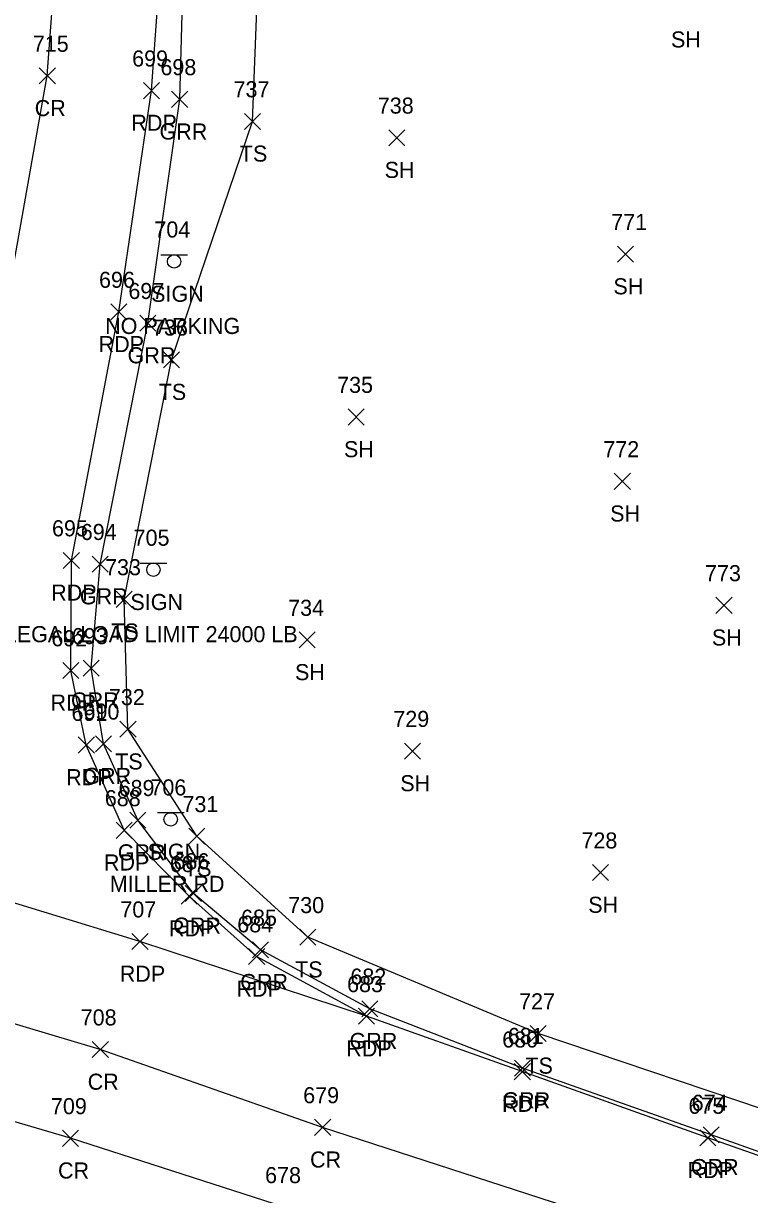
# Model space of a CAD drawing. Extents: x 1629176 to 1637209, y 606063 to 610167.
# Drawn here: x 1629985.1 to 1630075.4, y 606927.3 to 607073 of the extents above; entities that cross this region are included whole.
import ezdxf

# ---------------------------------------------------------------- set-up
doc = ezdxf.new("R2010")
doc.units = 0
for name, color, linetype in [('L_A', 7, 'Continuous'), ('L_I', 7, 'Continuous'), ('L_TIC', 7, 'Continuous'), ('LELB', 7, 'Continuous'), ('P_A', 7, 'Continuous'), ('P_I', 7, 'Continuous'), ('P_TIC', 7, 'Continuous'), ('PET', 7, 'Continuous'), ('PRC', 7, 'Continuous'), ('R_A', 7, 'Continuous'), ('R_I', 7, 'Continuous'), ('R_TIC', 7, 'Continuous'), ('RGR', 7, 'Continuous'), ('S_A', 7, 'Continuous'), ('S_C', 7, 'Continuous'), ('S_I', 7, 'Continuous'), ('SSGN', 7, 'Continuous')]:
    doc.layers.add(name, color=color, linetype=linetype)

msp = doc.modelspace()

# ---------------------------------------------------------------- linework, layer by layer
at = {"layer": 'L_TIC'}
for points in [[(1630012.65, 607059.81), (1630014.65, 607061.81)], [(1630014.65, 607059.81), (1630012.65, 607061.81)], [(1630030.58, 607057.78), (1630032.58, 607059.78)], [(1630032.58, 607057.78), (1630030.58, 607059.78)], [(1630059.03, 607043.3), (1630061.03, 607045.3)], [(1630061.03, 607043.3), (1630059.03, 607045.3)], [(1630002.56, 607030.17), (1630004.56, 607032.17)], [(1630004.56, 607030.17), (1630002.56, 607032.17)], [(1630025.52, 607023.04), (1630027.52, 607025.04)], [(1630027.52, 607023.04), (1630025.52, 607025.04)], [(1630058.63, 607015.04), (1630060.63, 607017.04)], [(1630060.63, 607015.04), (1630058.63, 607017.04)], [(1629996.66, 607000.36), (1629998.66, 607002.36)], [(1629998.66, 607000.36), (1629996.66, 607002.36)], [(1630071.27, 606999.62), (1630073.27, 607001.62)], [(1630073.27, 606999.62), (1630071.27, 607001.62)], [(1630019.43, 606995.31), (1630021.43, 606997.31)], [(1630021.43, 606995.31), (1630019.43, 606997.31)], [(1629997.15, 606984.2), (1629999.15, 606986.2)], [(1629999.15, 606984.2), (1629997.15, 606986.2)], [(1630032.52, 606981.49), (1630034.52, 606983.49)], [(1630034.52, 606981.49), (1630032.52, 606983.49)], [(1630005.71, 606970.89), (1630007.71, 606972.89)], [(1630007.71, 606970.89), (1630005.71, 606972.89)], [(1630055.9, 606966.37), (1630057.9, 606968.37)], [(1630057.9, 606966.37), (1630055.9, 606968.37)], [(1630019.53, 606958.33), (1630021.53, 606960.33)], [(1630021.53, 606958.33), (1630019.53, 606960.33)], [(1630048.16, 606946.36), (1630050.16, 606948.36)], [(1630050.16, 606946.36), (1630048.16, 606948.36)]]:
    msp.add_lwpolyline(points, dxfattribs=at)
at = {"layer": 'LELB'}
msp.add_lwpolyline([(1630084.2, 606935.53), (1630049.16, 606947.36), (1630020.53, 606959.33), (1630006.71, 606971.89), (1629998.15, 606985.2), (1629997.66, 607001.36), (1630003.56, 607031.17), (1630013.65, 607060.81), (1630014.9, 607093.95), (1630014.94, 607124.25), (1630010.97, 607149.73), (1630004.22, 607196.84), (1629997.94, 607243.02), (1629990.5, 607295.3), (1629983.84, 607333.53), (1629977.49, 607374.66), (1629974.09, 607413.89), (1629967.52, 607447.68), (1629960.93, 607485.98), (1629955.08, 607527.79), (1629952.27, 607562.54)], dxfattribs=at)
at = {"layer": 'P_TIC'}
for points in [[(1629987.12, 607065.47), (1629989.12, 607067.47)], [(1629989.12, 607065.47), (1629987.12, 607067.47)], [(1630000.08, 607063.64), (1630002.08, 607065.64)], [(1630002.08, 607063.64), (1630000.08, 607065.64)], [(1629996.01, 607036.11), (1629998.01, 607038.11)], [(1629998.01, 607036.11), (1629996.01, 607038.11)], [(1629990.11, 607005.2), (1629992.11, 607007.2)], [(1629992.11, 607005.2), (1629990.11, 607007.2)], [(1629990.03, 606991.52), (1629992.03, 606993.52)], [(1629992.03, 606991.52), (1629990.03, 606993.52)], [(1629991.97, 606982.24), (1629993.97, 606984.24)], [(1629993.97, 606982.24), (1629991.97, 606984.24)], [(1629996.68, 606971.63), (1629998.68, 606973.63)], [(1629998.68, 606971.63), (1629996.68, 606973.63)], [(1630004.77, 606963.44), (1630006.77, 606965.44)], [(1630006.77, 606963.44), (1630004.77, 606965.44)], [(1629998.64, 606957.79), (1630000.64, 606959.79)], [(1630000.64, 606957.79), (1629998.64, 606959.79)], [(1630013.15, 606955.94), (1630015.15, 606957.94)], [(1630015.15, 606955.94), (1630013.15, 606957.94)], [(1630026.81, 606948.5), (1630028.81, 606950.5)], [(1630028.81, 606948.5), (1630026.81, 606950.5)], [(1630026.81, 606948.5), (1630028.81, 606950.5)], [(1630028.81, 606948.5), (1630026.81, 606950.5)], [(1629993.71, 606944.36), (1629995.71, 606946.36)], [(1629995.71, 606944.36), (1629993.71, 606946.36)], [(1630046.19, 606941.61), (1630048.19, 606943.61)], [(1630048.19, 606941.61), (1630046.19, 606943.61)], [(1630021.36, 606934.68), (1630023.36, 606936.68)], [(1630023.36, 606934.68), (1630021.36, 606936.68)], [(1629990.01, 606933.32), (1629992.01, 606935.32)], [(1629992.01, 606933.32), (1629990.01, 606935.32)], [(1630069.26, 606933.37), (1630071.26, 606935.37)], [(1630071.26, 606933.37), (1630069.26, 606935.37)]]:
    msp.add_lwpolyline(points, dxfattribs=at)
at = {"layer": 'PET'}
for points in [[(1630027.81, 606949.5), (1630014.15, 606956.94), (1630005.77, 606964.44), (1629997.68, 606972.63), (1629992.97, 606983.24), (1629991.03, 606992.52), (1629991.11, 607006.2), (1629997.01, 607037.11), (1630001.08, 607064.64), (1630003.41, 607096.82), (1630003.02, 607124.17), (1630001.72, 607150.37), (1629998.35, 607185.15), (1629992.8, 607228.9), (1629986.61, 607277.03), (1629979.67, 607327.82), (1629973.81, 607373.57)], [(1630115.59, 606918.47), (1630070.26, 606934.37), (1630047.19, 606942.61), (1630027.81, 606949.5), (1629999.64, 606958.79), (1629963.88, 606969.73), (1629916.37, 606983.66), (1629883.8, 606991.87), (1629841.7, 607003.38), (1629794.53, 607014.94), (1629751.13, 607024.85), (1629703.98, 607035.26), (1629666.74, 607043.02), (1629621.43, 607051.04), (1629588.28, 607056.93), (1629542.89, 607063.67), (1629493.94, 607070.34), (1629447.94, 607075.86), (1629406.53, 607080.22), (1629360.37, 607084.28), (1629316.73, 607087.48), (1629269.81, 607090.12), (1629227.29, 607092.24), (1629182.92, 607093.47)]]:
    msp.add_lwpolyline(points, dxfattribs=at)
at = {"layer": 'PRC'}
for points in [[(1629963.88, 606969.73), (1629972.76, 606997.52), (1629981.25, 607028.09), (1629988.12, 607066.47), (1629990.62, 607100.29), (1629990.61, 607124.69), (1629989.69, 607149.78), (1629986.77, 607182.68), (1629981.28, 607228.24), (1629975.13, 607276.5), (1629968.07, 607326.63), (1629961.78, 607372.25), (1629956.91, 607408.66), (1629951.88, 607446.34), (1629946.39, 607483.34), (1629940.59, 607526.71), (1629934.53, 607569.1), (1629928.23, 607613.94), (1629922.81, 607653.99), (1629916.48, 607702.82)], [(1630110.18, 606905.77), (1630065.36, 606921.68), (1630022.36, 606935.68), (1629994.71, 606945.36), (1629959.54, 606955.86), (1629913.54, 606969.37), (1629877.41, 606979.26), (1629837.69, 606989.99), (1629791.63, 607000.82), (1629746.42, 607011.44), (1629699.59, 607021.37), (1629664.04, 607028.34), (1629619.43, 607036.79), (1629585.72, 607042.18), (1629539.96, 607049.3), (1629491.45, 607056.02), (1629445.88, 607061.28), (1629404.36, 607066.23), (1629358.89, 607069.49), (1629314.63, 607073.29), (1629269.37, 607075.36), (1629226.58, 607077.32), (1629182.35, 607078.58)], [(1630105.99, 606894.95), (1630061.18, 606910.94), (1630017.61, 606925.74), (1629991.01, 606934.32), (1629955.3, 606944.84), (1629910.77, 606959.12), (1629874.52, 606969.06), (1629834.93, 606979.4), (1629788.74, 606990.13), (1629743.3, 607000.68), (1629697.98, 607010.33), (1629662.17, 607017.56), (1629618.2, 607025.81), (1629583.59, 607031.56), (1629540.4, 607037.95), (1629489.63, 607045.02), (1629444.26, 607050.14), (1629402.79, 607054.66), (1629359.1, 607058.26), (1629313.06, 607061.88), (1629268.47, 607063.97), (1629226.23, 607065.89), (1629182.22, 607066.96)]]:
    msp.add_lwpolyline(points, dxfattribs=at)
at = {"layer": 'R_TIC'}
for points in [[(1630003.58, 607062.56), (1630005.58, 607064.56)], [(1630005.58, 607062.56), (1630003.58, 607064.56)], [(1629999.61, 607034.72), (1630001.61, 607036.72)], [(1630001.61, 607034.72), (1629999.61, 607036.72)], [(1629993.69, 607004.74), (1629995.69, 607006.74)], [(1629995.69, 607004.74), (1629993.69, 607006.74)], [(1629992.57, 606991.79), (1629994.57, 606993.79)], [(1629994.57, 606991.79), (1629992.57, 606993.79)], [(1629994.11, 606982.4), (1629996.11, 606984.4)], [(1629996.11, 606982.4), (1629994.11, 606984.4)], [(1629998.39, 606972.89), (1630000.39, 606974.89)], [(1630000.39, 606972.89), (1629998.39, 606974.89)], [(1630005.28, 606963.78), (1630007.28, 606965.78)], [(1630007.28, 606963.78), (1630005.28, 606965.78)], [(1630013.62, 606956.76), (1630015.62, 606958.76)], [(1630015.62, 606956.76), (1630013.62, 606958.76)], [(1630027.22, 606949.43), (1630029.22, 606951.43)], [(1630029.22, 606949.43), (1630027.22, 606951.43)], [(1630046.22, 606942.05), (1630048.22, 606944.05)], [(1630048.22, 606942.05), (1630046.22, 606944.05)], [(1630069.66, 606933.74), (1630071.66, 606935.74)], [(1630071.66, 606933.74), (1630069.66, 606935.74)]]:
    msp.add_lwpolyline(points, dxfattribs=at)
at = {"layer": 'RGR'}
msp.add_lwpolyline([(1630115.67, 606918.76), (1630070.66, 606934.74), (1630047.22, 606943.05), (1630028.22, 606950.43), (1630014.62, 606957.76), (1630006.28, 606964.78), (1629999.39, 606973.89), (1629995.11, 606983.4), (1629993.57, 606992.79), (1629994.69, 607005.74), (1630000.61, 607035.72), (1630004.58, 607063.56), (1630005.51, 607096.84), (1630005.28, 607124.06), (1630003.63, 607150.96), (1629999.95, 607185.04), (1629994.67, 607228.89), (1629988.47, 607276.39), (1629981.73, 607327.94), (1629975.48, 607374.16), (1629971.69, 607411.49)], dxfattribs=at)
at = {"layer": 'SSGN'}
for p, q in [((1630002.24, 607044.22), (1630005.57, 607044.22)), ((1630003.89, 607043.39), (1630003.89, 607043.39)), ((1629999.67, 607005.88), (1630003, 607005.88)), ((1630001.31, 607005.05), (1630001.31, 607005.05)), ((1630001.81, 606974.83), (1630005.14, 606974.83)), ((1630003.46, 606973.99), (1630003.46, 606973.99))]:
    msp.add_line(p, q, dxfattribs=at)
for centre in [(1630003.89, 607043.39), (1630001.31, 607005.05), (1630003.46, 606973.99)]:
    msp.add_circle(centre, 0.833, dxfattribs=at)

# ---------------------------------------------------------------- texts
at = {"layer": 'L_A'}
for s, p in [('SH', (1630065.68, 607070.01)), ('TS', (1630012.06, 607055.81)), ('SH', (1630030.07, 607053.78)), ('SH', (1630058.52, 607039.3)), ('TS', (1630001.97, 607026.17)), ('SH', (1630025.01, 607019.04)), ('SH', (1630058.11, 607011.04)), ('TS', (1629996.07, 606996.36)), ('SH', (1630070.76, 606995.62)), ('SH', (1630018.92, 606991.31)), ('TS', (1629996.56, 606980.2)), ('SH', (1630032.01, 606977.49)), ('TS', (1630005.12, 606966.89)), ('SH', (1630055.39, 606962.37)), ('TS', (1630018.94, 606954.33)), ('TS', (1630047.57, 606942.36))]:
    msp.add_text(s, height=2, dxfattribs=at).set_placement(p)
at = {"layer": 'L_I'}
for s, p in [('737', (1630011.28, 607063.81)), ('738', (1630029.22, 607061.78)), ('771', (1630058.24, 607047.3)), ('736', (1630001.14, 607034.17)), ('735', (1630024.16, 607027.04)), ('772', (1630057.26, 607019.04)), ('733', (1629995.3, 607004.36)), ('773', (1630069.91, 607003.62)), ('734', (1630018.07, 606999.31)), ('732', (1629995.78, 606988.2)), ('729', (1630031.15, 606985.49)), ('731', (1630004.92, 606974.89)), ('728', (1630054.54, 606970.37)), ('730', (1630018.08, 606962.33)), ('727', (1630046.79, 606950.36))]:
    msp.add_text(s, height=2, dxfattribs=at).set_placement(p)
at = {"layer": 'P_A'}
for s, p in [('CR', (1629986.55, 607061.47)), ('RDP', (1629998.57, 607059.64)), ('RDP', (1629994.5, 607032.11)), ('RDP', (1629988.6, 607001.2)), ('RDP', (1629988.52, 606987.52)), ('RDP', (1629990.46, 606978.24)), ('RDP', (1629995.16, 606967.63)), ('RDP', (1630003.25, 606959.44)), ('RDP', (1629997.13, 606953.79)), ('RDP', (1630011.64, 606951.94)), ('RDP', (1630025.3, 606944.5)), ('RDP', (1630025.3, 606944.5)), ('CR', (1629993.14, 606940.36)), ('RDP', (1630044.67, 606937.61)), ('CR', (1629989.45, 606929.32)), ('CR', (1630020.79, 606930.68)), ('RDP', (1630067.74, 606929.37))]:
    msp.add_text(s, height=2, dxfattribs=at).set_placement(p)
at = {"layer": 'P_I'}
for s, p in [('715', (1629986.32, 607069.47)), ('699', (1629998.67, 607067.64)), ('696', (1629994.55, 607040.11)), ('695', (1629988.7, 607009.2)), ('692', (1629988.62, 606995.52)), ('691', (1629991.13, 606986.24)), ('688', (1629995.27, 606975.63)), ('687', (1630003.36, 606967.44)), ('707', (1629997.2, 606961.79)), ('684', (1630011.74, 606959.94)), ('683', (1630025.4, 606952.5)), ('683', (1630025.4, 606952.5)), ('708', (1629992.27, 606948.36)), ('680', (1630044.69, 606945.61)), ('679', (1630019.94, 606938.68)), ('709', (1629988.57, 606937.32)), ('675', (1630067.85, 606937.37)), ('678', (1630015.2, 606928.74))]:
    msp.add_text(s, height=2, dxfattribs=at).set_placement(p)
at = {"layer": 'R_A'}
for p in [(1630002.07, 607058.56), (1629998.1, 607030.72), (1629992.17, 607000.74), (1629991.06, 606987.79), (1629992.6, 606978.4), (1629996.88, 606968.89), (1630003.77, 606959.78), (1630012.11, 606952.76), (1630025.7, 606945.43), (1630044.71, 606938.05), (1630068.15, 606929.74)]:
    msp.add_text('GRR', height=2, dxfattribs=at).set_placement(p)
at = {"layer": 'R_I'}
for s, p in [('698', (1630002.18, 607066.56)), ('697', (1629998.2, 607038.72)), ('694', (1629992.28, 607008.74)), ('693', (1629991.16, 606995.79)), ('690', (1629992.62, 606986.4)), ('689', (1629996.98, 606976.89)), ('686', (1630003.81, 606967.78)), ('685', (1630012.21, 606960.76)), ('682', (1630025.81, 606953.43)), ('681', (1630045.38, 606946.05)), ('674', (1630068.25, 606937.74))]:
    msp.add_text(s, height=2, dxfattribs=at).set_placement(p)
at = {"layer": 'S_A'}
for p in [(1630001.03, 607038.37), (1629998.45, 607000.03), (1630000.59, 606968.97)]:
    msp.add_text('SIGN', height=2, dxfattribs=at).set_placement(p)
at = {"layer": 'S_C'}
for s, p in [('NO PARKING', (1629995.31, 607034.37)), ('STOP & LEGAL LOAD LIMIT 24000 LB', (1629972.28, 606996.03)), ('MILLER RD', (1629995.89, 606964.97))]:
    msp.add_text(s, height=2, dxfattribs=at).set_placement(p)
at = {"layer": 'S_I'}
for s, p in [('704', (1630001.43, 607046.37)), ('705', (1629998.85, 607008.03)), ('706', (1630000.94, 606976.97))]:
    msp.add_text(s, height=2, dxfattribs=at).set_placement(p)

doc.saveas('drawing.dxf')
